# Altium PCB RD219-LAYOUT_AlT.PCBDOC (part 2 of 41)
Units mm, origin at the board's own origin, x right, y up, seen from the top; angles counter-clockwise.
Board outline 209.75 x 159.97 mm, 2 copper layers (TOP, BOTTOM), stack 0 mm thick; 398 components, 199 nets, 1469 pads, 0 vias.
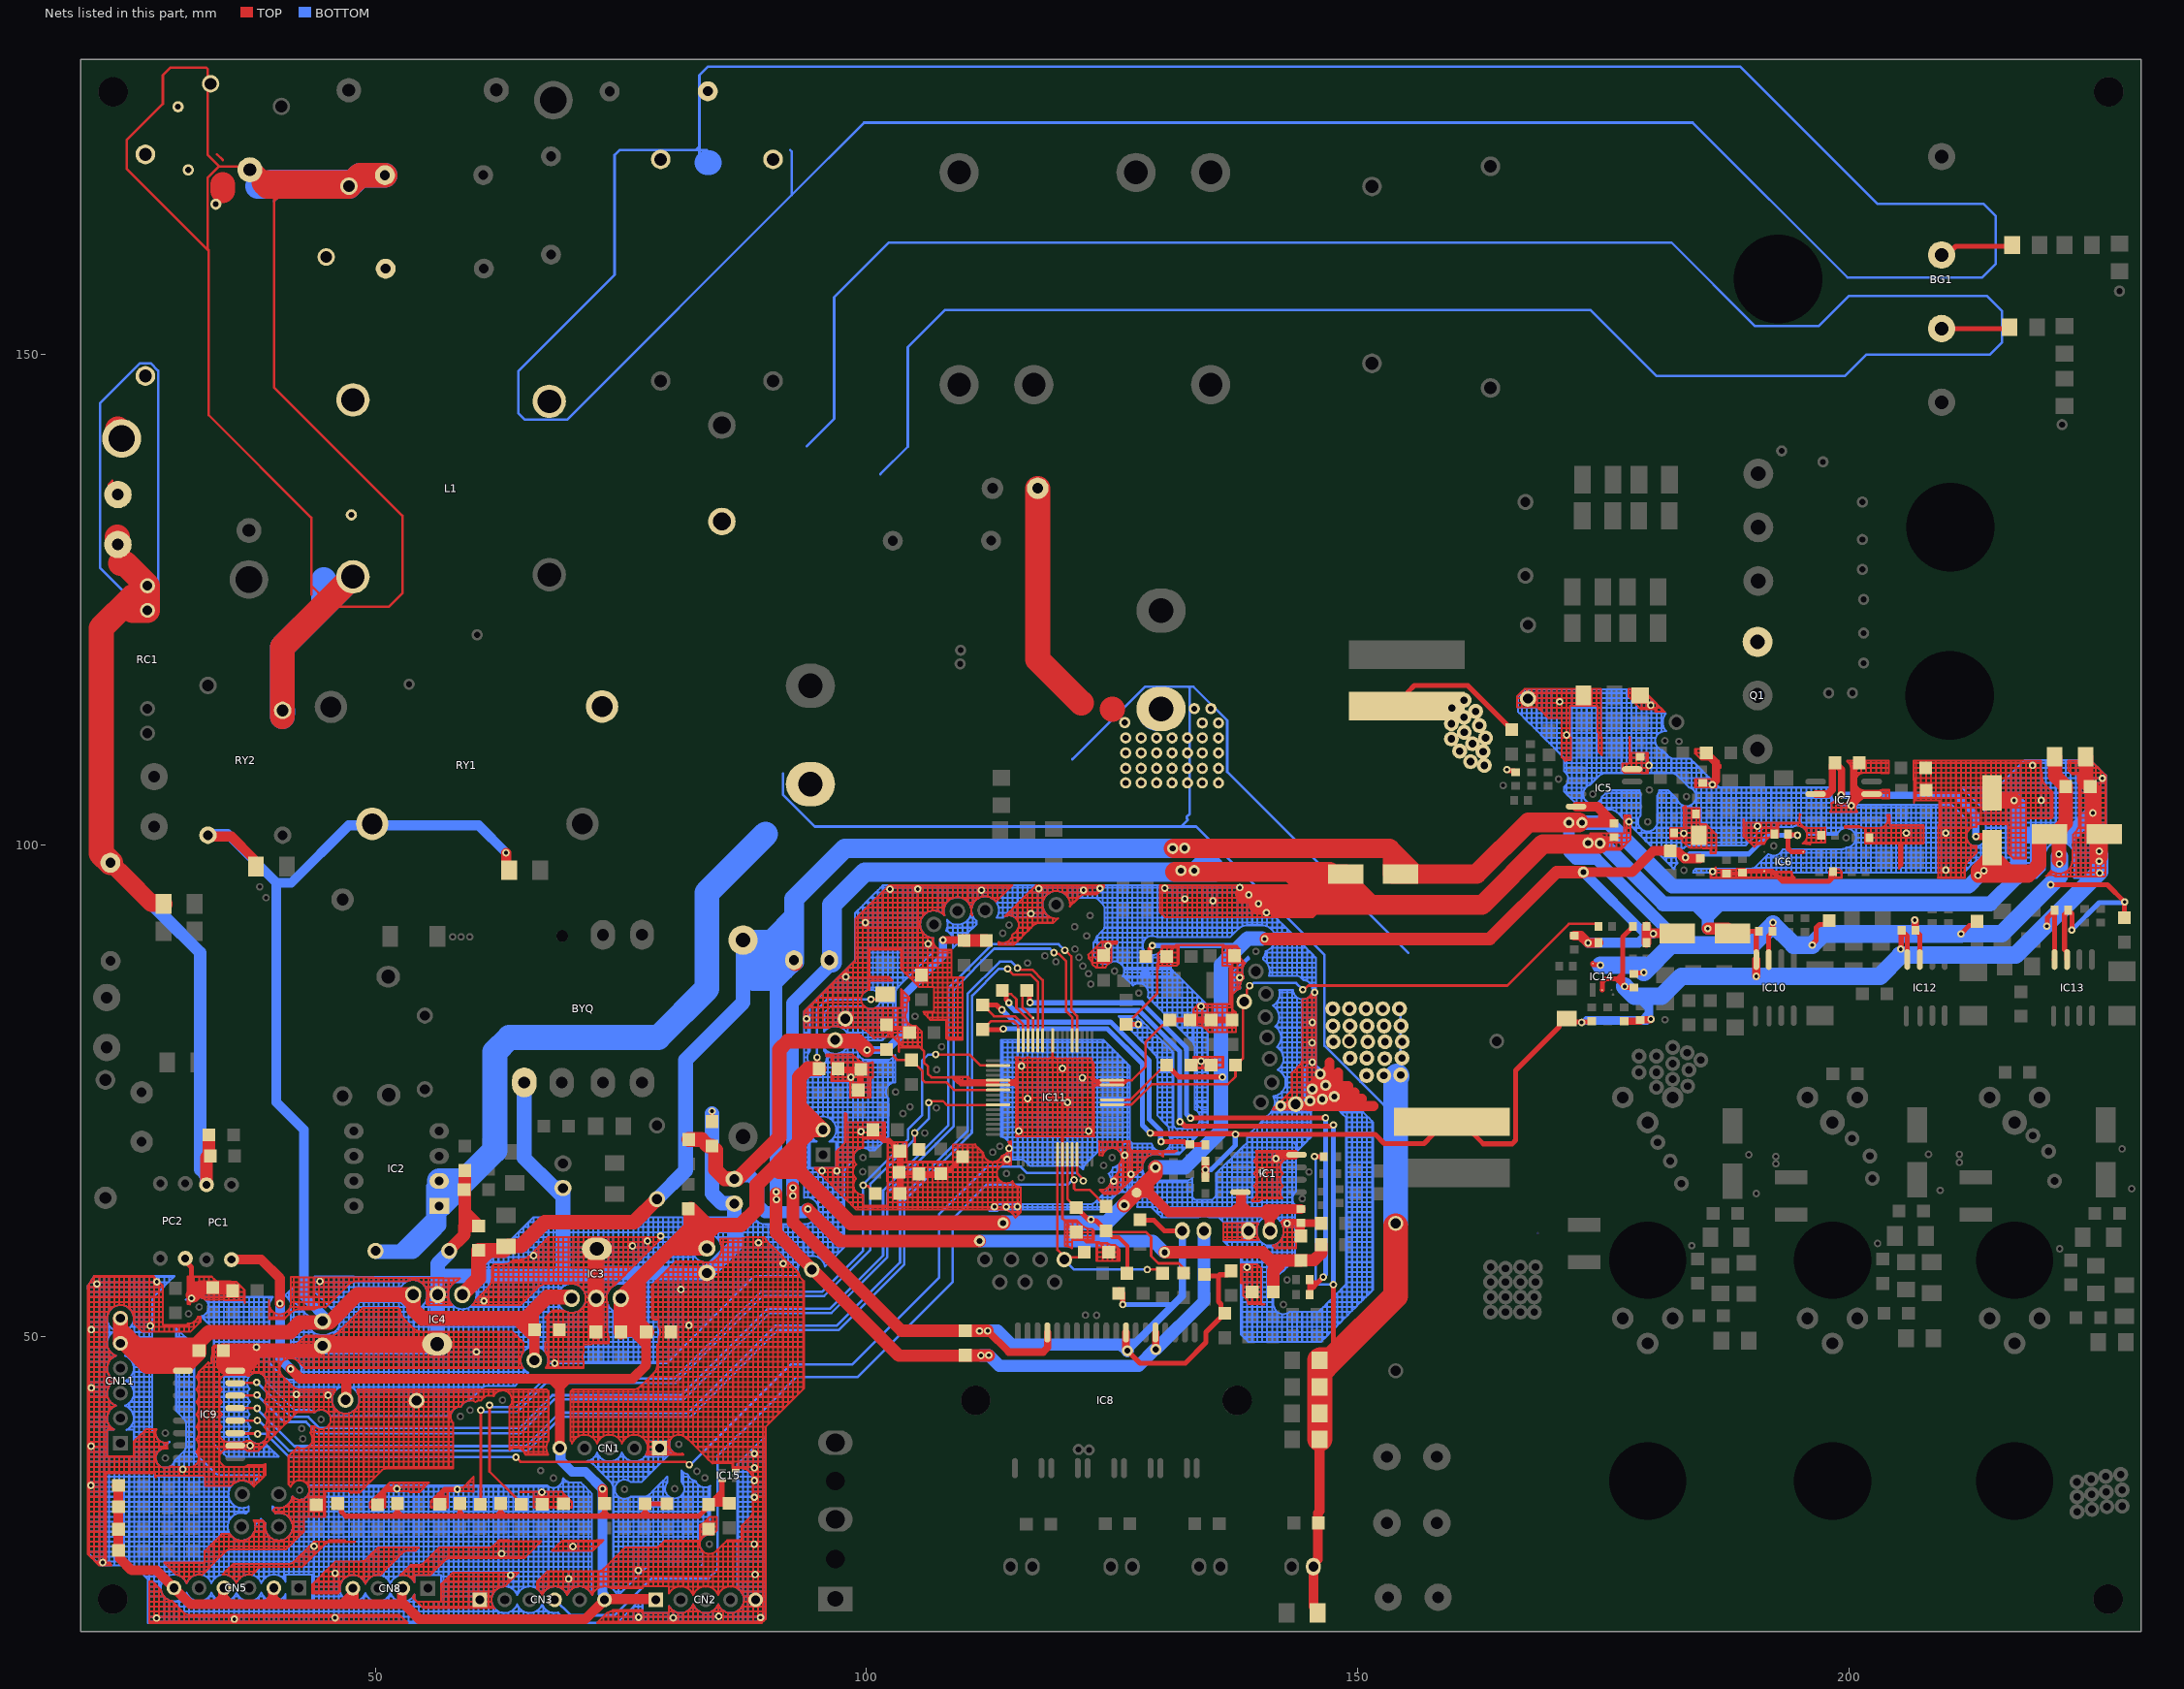
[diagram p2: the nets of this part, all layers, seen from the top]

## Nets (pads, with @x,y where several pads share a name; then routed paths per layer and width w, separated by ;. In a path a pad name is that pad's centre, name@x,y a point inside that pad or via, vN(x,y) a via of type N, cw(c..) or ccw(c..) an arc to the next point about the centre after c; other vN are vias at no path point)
+5V: C16.2 C23.1 C46.1 C49.2 C50.2 C51.2 C52.2 C53.2 C64.1 C65.1 C68.2 C87.2 C110.1 CN1.5 CN2.1 CN3.6 CN5.2 CN5.4 CN5.6 CN8.2 CN8.4 CN9.2 D13.2 EC5.1 EC16.1 EC20.1 FB1.2 IC1.8 IC3.3 IC6.8 IC11.43 IC11.56 IC15.5 LED1.1 LED2.1 LED3.1 LED4.1 LED5.1 pad.@40.296,53.386 pad.@41.376,46.714 pad.@73.135,34.512 pad.@94.965,78.418 pad.@100.444,84.334 pad.@113.9,61.576 pad.@122.835,61.935 pad.@126.222,63.389 pad.@127.49,64.656 pad.@129.41,67.234 pad.@129.091,89.799 pad.@136.214,76.427 pad.@140.523,90.485 pad.@172.957,97.267 pad.@173.434,90.067 pad.@180.09,91.02 pad.@183.356,98.756 pad.@194.752,101.026 PC1.C R13.2 R18.2 R50.2 R51.2 R81.2 R92.1 R101.2 R108.1 R145.2 R148.2 R149.2 R150.2 TP3.1 | length 561.4
  TOP w0.254: pad.@94.965,78.418 94.965,77.496 C87.2@95.184,77.277 ; pad.@100.444,84.334 101.606,84.334 D13.2@101.915,84.643 ; IC11.43@120.437,68.556 120.437,64.038 C64.1@121.346,63.129 ; R108.1@124.394,60.767 124.521,60.64 128.458,60.64 128.966,60.132 128.966,58.227 129.728,57.465 131.76,57.465 R51.2@132.776,56.449 ; IC11.56@124.987,74.106 126.852,74.106 129.881,77.135 130.018,77.135 C65.1@130.541,77.658 ; R81.2@128.328,88.728 128.328,88.88 R81.2@128.431,88.982
  TOP w0.4: R108.1@124.521,60.64 125.029,60.132 125.664,60.132 126.553,59.243 R50.2@126.553,56.83
  TOP w0.508: LED4.1@23.429,34.808 LED4.1@23.48,34.859 ; C49.2@46.162,33.03 46.558,32.634 46.558,32.177 46.995,31.74 51.806,31.74 ; C50.2@52.258,33.03 52.258,32.192 ; C51.2@58.618,33.024 58.618,32.065 ; C52.2@62.762,33.024 62.762,32.192 ; C53.2@73.709,32.661 C53.2@73.34,33.03 73.34,32.192 ; R148.2@79.677,32.983 79.67,32.99 77.477,32.99 R149.2@77.47,32.997 77.47,32.192 ; C110.1@83.881,32.7 82.921,31.74 77.785,31.74 ; C110.1@83.881,32.861 C110.1@83.936,32.917 C110.1@84,32.98 ; 85.29,35.148 85.29,34.27 ; R150.2@86.027,33.044 85.963,32.98 85.024,32.98 ; C64.1@121.346,63.129 122.575,61.9 122.784,61.9 122.792,61.892 122.881,61.803 123.358,61.803 R108.1@124.394,60.767 ; R81.2@128.431,88.707 128.827,89.103 128.827,89.466 129.091,89.73 pad.@129.091,89.799 ; C65.1@130.541,77.658 131.772,76.427 pad.@136.214,76.427 ; pad.@194.752,101.026 194.703,101.075 193.879,101.075 C16.2@193.801,101.153 193.801,99.691 194.158,99.334 IC6.8@195.33,99.334 ; 51.806,31.74 52.258,32.192 ; 51.806,31.74 52.258,31.74 ; 52.258,31.74 52.71,31.74 ; 52.258,31.74 52.258,32.192 ; 52.258,32.192 52.71,31.74 ; 52.71,31.74 58.294,31.74 ; 58.294,31.74 58.618,32.065 ; 58.294,31.74 58.608,31.74 ; 58.608,31.74 58.989,31.74 ; 58.608,31.74 58.618,31.751 58.618,32.065 ; 58.618,32.065 58.664,32.065 58.989,31.74 ; 58.989,31.74 62.31,31.74 ; 62.31,31.74 62.799,31.74 ; 62.31,31.74 62.762,32.192 ; 62.762,32.192 63.18,31.774 63.18,31.74 ; 62.762,32.192 62.762,31.778 62.799,31.74 ; 62.799,31.74 63.18,31.74 ; 63.18,31.74 72.888,31.74 ; 72.888,31.74 73.34,32.192 ; 72.888,31.74 73.34,31.74 ; 73.34,31.74 73.792,31.74 ; 73.34,31.74 73.34,32.192 ; 73.34,32.192 73.792,31.74 ; 73.792,31.74 77.15,31.74 ; 77.15,31.74 77.404,31.74 ; 77.15,31.74 77.15,31.872 77.47,32.192 ; 77.404,31.74 77.785,31.74 ; 77.404,31.74 77.47,31.807 77.47,32.192 ; 77.47,32.192 77.785,31.877 77.785,31.74 ; C110.1@84,32.98 84.645,33.625 ; C110.1@84,32.98 84.643,32.98 ; 84.643,32.98 85.024,32.98 ; 84.643,32.98 84.645,32.983 84.645,33.625 ; 84.645,33.625 84.968,33.948 ; 84.968,33.948 85.29,34.27 ; 84.968,33.948 84.968,33.037 85.024,32.98 ; 85.024,32.98 85.29,33.247 85.29,34.27
  TOP w1: LED4.1@23.861,34.859 LED3.1@23.861,32.7 LED2.1@23.861,30.414 LED1.1@23.861,28.255 24.011,28.105 24.011,27.421 25.209,26.223 27.747,26.223 CN5.6@29.525,24.445 31.176,22.794 33.843,22.794 ; CN5.4@34.605,24.445 34.509,24.349 34.509,23.46 ; PC1.C@35.367,57.846 38.4,57.846 40.296,55.95 pad.@40.296,53.386 ; CN5.2@39.685,24.445 39.589,24.349 39.589,23.401 ; pad.@41.376,46.714 42.354,45.737 47.051,45.737 ; TP3.1@46.939,43.576 46.959,43.596 47.051,43.688 47.051,45.737 ; CN8.4@47.59,23.714 46.67,22.794 ; CN8.4@47.729,24.407 47.734,24.402 47.824,24.311 47.824,23.181 48.194,22.811 48.194,22.794 ; 52.713,22.794 48.194,22.794 ; 52.713,23.249 52.713,24.311 CN8.2@52.809,24.407 ; 52.928,22.794 54.452,21.27 71.397,21.27 73.34,23.213 CN3.6@73.34,23.241 73.34,23.302 CN2.1@78.547,23.302 ; CN1.5@68.768,38.542 68.768,44.892 ; pad.@73.135,34.512 73.19,34.457 73.19,33.18 C53.2@73.34,33.03 ; LED5.1@74.991,50.48 76.312,50.48 ; IC3.3@74.991,53.909 75.179,53.721 76.227,53.721 76.801,53.147 ; C23.1@77.658,50.48 C23.1@77.582,50.48 ; R101.2@172.019,90.804 172.697,90.804 pad.@173.434,90.067 174.457,90.067 R92.1@174.494,90.104 ; pad.@172.957,97.267 177.904,97.267 180.089,99.451 R18.2@181.798,99.451 181.948,99.301 182.634,99.301 183.257,98.678 pad.@183.356,98.678 ; R145.2@179.385,90.104 179.385,90.93 ; C68.2@179.385,91.755 179.385,90.93 ; EC20.1@182.54,91.046 179.502,91.046 179.385,90.93 ; pad.@183.356,98.756 183.464,98.647 R13.2@184.815,98.647 ; 33.843,22.794 35.176,22.794 ; 33.843,22.794 34.509,23.46 ; 34.509,23.46 35.176,22.794 ; 35.176,22.794 38.982,22.794 ; 38.982,22.794 40.193,22.794 ; 38.982,22.794 39.589,23.401 ; 39.589,23.401 40.193,22.797 40.193,22.794 ; 40.193,22.794 46.67,22.794 ; 46.67,22.794 48.194,22.794 ; 47.051,45.737 67.923,45.737 ; 67.923,45.737 68.768,45.737 ; 67.923,45.737 68.768,44.892 ; 68.768,44.892 69.613,45.737 ; 68.768,44.892 68.768,45.737 ; 68.768,45.737 69.613,45.737 ; 69.613,45.737 76.217,45.737 77.582,47.102 77.582,49.21 ; 76.312,50.48 C23.1@77.582,50.48 ; 76.312,50.48 77.582,49.21 ; 77.582,49.21 C23.1@77.582,50.48
  TOP w1.016: pad.@127.49,64.656 128.76,64.656 ; 128.125,65.291 128.442,64.974 ; 128.76,65.291 128.76,64.656 ; 138.11,64.374 138.11,63.434 ; EC16.1@141.072,60.767 141.02,60.819 141.02,62.048 ; C46.1@144.206,62.991 141.962,62.991 ; 128.76,64.656 130.744,62.672 137.348,62.672 ; 137.348,62.672 138.11,63.434 ; 137.348,62.672 138.11,62.672 ; 138.11,62.672 138.745,62.672 ; 138.11,62.672 138.11,63.434 ; 138.11,63.434 138.745,62.799 138.745,62.672 ; 138.745,62.672 140.396,62.672 ; 140.396,62.672 141.02,62.048 ; 140.396,62.672 140.715,62.991 141.962,62.991 ; 141.02,62.048 141.962,62.991
  TOP w1.27: pad.@140.635,90.485 163.435,90.485 170.232,97.283 pad.@172.941,97.283
  TOP w1.5: LED5.1@74.991,50.48 74.991,51.369 ; C23.1@77.658,50.48 76.801,51.337 ; C87.2@95.184,77.277 94.031,77.277 93.152,76.398 93.152,73.467 ; pad.@113.9,61.576 113.895,61.581 98.386,61.581 93.152,66.815 ; pad.@126.222,63.389 pad.@127.49,64.656 128.125,65.291 129.41,66.576 pad.@129.41,67.234 ; 74.991,51.369 74.991,52.766 ; 74.991,51.369 76.769,51.369 76.801,51.337 ; 74.991,52.766 IC3.3@74.991,53.909 74.991,53.973 76.801,55.782 ; 74.991,52.766 76.42,52.766 76.801,53.147 ; 76.801,51.337 76.801,53.147 ; 76.801,53.147 76.801,55.782 ; 76.801,55.782 80.008,58.989 ; 80.008,58.989 EC5.1@83.731,58.989 ; 80.008,58.989 80.973,59.954 ; 80.973,59.954 82.789,59.954 ; 80.973,59.954 82.103,61.085 ; 82.103,61.085 84.364,61.085 ; 82.103,61.085 82.103,62.977 83.727,61.353 84.633,61.353 ; 82.103,61.085 82.103,60.64 82.789,59.954 ; 82.789,59.954 83.662,59.081 83.662,59.059 EC5.1@83.731,58.989 ; EC5.1@83.731,58.989 EC5.1@83.754,58.989 83.754,60.474 84.364,61.085 ; 84.364,61.085 84.633,61.353 ; 84.633,61.353 87.202,61.353 88.834,62.985 88.834,65.466 93.152,69.784 ; 93.152,66.815 93.152,68.705 ; 93.152,66.815 91.072,66.815 92.962,68.705 93.152,68.705 ; 93.152,68.705 93.152,69.784 ; 93.152,69.784 94.422,71.054 CN9.2@95.565,71.054 94.549,72.07 ; 93.152,69.784 93.152,71.562 ; 93.152,71.562 93.66,72.07 94.549,72.07 ; 93.152,71.562 93.152,73.467 ; 93.152,73.467 94.549,72.07
  BOTTOM w0.254: pad.@94.965,78.418 94.965,83.281 96.018,84.334 pad.@100.444,84.334
  BOTTOM w0.508: pad.@129.091,89.799 136.713,89.799 ; 137.025,88.776 136.713,89.088 136.713,89.799 ; 137.977,89.729 137.907,89.799 136.713,89.799 ; pad.@183.356,98.756 183.415,98.756 183.78,99.121 189.799,99.121 191.704,101.026 pad.@194.752,101.026 pad.@194.773,101.026
  BOTTOM w1: pad.@40.32,53.147 40.32,47.77 pad.@41.376,46.714 ; CN1.5@68.768,38.669 68.864,38.573 68.864,37.43 70.038,36.256 71.391,36.256 pad.@73.135,34.512 73.135,23.86 73.244,23.751 73.244,23.398 CN3.6@73.34,23.302 ; pad.@172.957,97.267 172.984,97.267 179.231,91.02 ; pad.@173.434,90.067 173.471,90.104 178.594,90.104 179.51,91.02 pad.@180.09,91.02
  BOTTOM w1.5: pad.@113.9,61.576 113.917,61.593 124.426,61.593 pad.@126.222,63.389 ; pad.@129.41,67.234 132.392,67.234 136.078,70.92 136.078,87.83 137.025,88.776 137.977,89.729 138.772,90.524 pad.@140.242,90.524
+12V: C48.1 C83.1 CN11.5 CN11.6 D1.2 D14.2 EC6.1 IC3.1 IC4.3 IC9.9 pad.@63.307,99.248 RY1.3 RY2.3 TP2.1 | length 180.2
  TOP w0.508: D1.2@63.307,97.797 63.334,97.77 D1.2@63.634,97.47
  TOP w1: RY2.3@32.974,101.036 33.107,100.903 35.363,100.903 37.553,98.713 37.553,98.151 D14.2@37.853,97.851 ; pad.@63.307,99.248 63.334,99.221 D1.2@63.334,97.77 ; TP2.1@66.15,47.61 66.192,47.653 66.192,50.656 C83.1@66.235,50.698
  TOP w1.016: D1.2@63.337,97.567 D1.2@63.434,97.47
  TOP w1.5: CN11.5@24.064,49.337 24.064,50.828 ; CN11.6@24.064,51.877 24.064,50.828 ; IC3.1@69.991,53.909 69.991,53.932 69.921,54.001 69.899,54.001 69.864,54.036 67.498,54.036 65.898,52.436 ; 24.064,50.828 24.81,50.083 25.715,49.177 ; 25.715,49.177 27.951,49.177 ; 25.715,49.177 26.803,48.089 29.039,48.089 ; 25.715,49.177 24.572,49.177 26.317,47.432 ; 26.317,47.432 27.112,47.432 ; 26.317,47.432 26.774,46.975 27.569,46.975 ; 27.112,47.432 28.382,47.432 29.039,48.089 ; 27.112,47.432 27.569,46.975 ; 27.569,46.975 30.152,46.975 ; 27.951,49.177 30.668,49.177 ; 27.951,49.177 29.039,48.089 ; 29.039,48.089 30.436,48.089 30.668,48.321 ; 29.039,48.089 30.152,46.975 ; 30.152,46.975 30.668,46.975 ; 30.668,46.975 30.684,46.975 32.065,48.356 C48.1@32.065,48.575 ; 30.668,46.975 30.668,48.321 ; 30.668,48.321 30.668,49.177 ; 30.668,49.177 31.463,49.177 C48.1@32.065,48.575 ; C48.1@32.065,48.575 32.065,49.474 33.056,50.466 41.322,50.466 42.312,51.456 45.337,51.456 48.171,54.29 52.893,54.29 ; 52.893,54.29 IC4.3@53.862,54.29 53.891,54.261 53.891,53.292 ; 52.893,54.29 53.378,53.805 53.891,53.292 ; 53.891,53.292 53.891,52.756 54.77,51.877 64.501,51.877 ; 64.501,51.877 65.898,50.48 65.898,52.436 ; 64.501,51.877 65.339,51.877 65.898,52.436
  BOTTOM w1: RY2.3@32.8,101.153 34.986,101.153 39.939,96.2 ; EC6.1@45.273,51.456 45.273,51.569 42.733,54.109 42.733,71.054 39.939,73.848 39.939,96.2 ; RY1.3@49.688,102.187 49.542,102.042 47.305,102.042 41.463,96.2 39.939,96.2
  BOTTOM w1.016: RY1.3@49.688,102.187 49.833,102.042 60.513,102.042 pad.@63.307,99.248
+15V: C15.2 C21.2 C24.1 C31.1 C57.1 C58.1 C74.1 C76.1 C82.2 C89.2 D4.2 EC4.1 EC7.1 EC12.1 EC15.1 EC17.1 IC4.1 IC5.8 IC7.6 IC8.5 IC10.3 IC12.3 IC13.3 IC14.5 pad.@90.81,64.745 pad.@90.834,63.961 pad.@111.642,48.099 pad.@112.44,48.122 pad.@129.444,48.708 pad.@131.167,99.688 pad.@132.377,99.725 pad.@171.484,102.315 pad.@172.821,102.315 pad.@174.692,87.804 pad.@179.113,87.071 pad.@192.252,92.157 pad.@196.25,89.857 pad.@199.188,105.13 pad.@206.69,92.39 pad.@211.387,90.991 pad.@212.913,100.905 pad.@213.122,96.948 pad.@213.732,97.42 pad.@220.519,95.997 pad.@221.377,99.107 pad.@221.422,98.105 pad.@222.674,91.382 pad.@228.053,94.244 R90.2 R125.2 R132.2 TP1.1 ZD2.2 ZD4.2 | length 513.5
  TOP w0.508: IC8.5@129.406,50.437 IC8.5@129.424,50.419 ; pad.@129.424,48.729 129.425,48.727 pad.@129.444,48.708 ; IC14.5@173.924,87.978 173.924,87.893 173.964,87.853 174.644,87.853 pad.@174.692,87.804 ; pad.@179.113,87.071 179.064,87.022 178.205,87.022 C89.2@178.115,86.932 ; IC10.3@191.831,88.382 191.831,90.816 192.212,91.197 C58.1@192.212,91.247 192.232,91.267 192.232,92.137 pad.@192.252,92.157 ; pad.@196.25,89.857 196.25,89.925 196.657,90.332 196.657,91.628 196.983,91.954 197.597,91.954 R90.2@197.993,92.35 ; IC7.6@196.619,105.199 IC7.6@196.601,105.217 IC7.6@196.619,105.235 ; C74.1@206.755,91.374 206.755,91.324 207.198,90.881 IC12.3@207.198,88.382 IC12.3@207.216,88.4 ; pad.@211.387,90.991 212.263,91.867 212.644,91.867 R125.2@213.04,92.263 ; EC15.1@213.818,100.905 214.564,100.159 EC15.1@214.564,99.744 ; pad.@220.519,95.997 226.3,95.997 pad.@228.053,94.244 228.04,94.23 228.04,92.658 R132.2@228.026,92.644 ; IC13.3@222.184,88.382 222.184,89.157 221.93,89.411 221.93,92.975 222.165,93.21 222.165,93.26 C76.1@222.311,93.406 C76.1@222.457,93.26 ; C76.1@222.384,93.333 222.691,93.026 222.691,91.399 pad.@222.674,91.382 ; C89.2@178.115,86.932 177.985,86.802 177.985,87.012 177.919,87.078 177.969,87.078 C89.2@178.115,86.932
  TOP w0.762: IC8.5@129.424,50.419 129.425,50.418 pad.@129.425,48.727 ; IC7.6@196.601,105.217 197.862,105.217 198.308,105.663 198.308,108.138 C21.2@198.562,108.392 199.248,107.706 199.248,105.189 pad.@199.188,105.13 ; pad.@206.69,92.39 206.736,92.344 206.736,91.343 C74.1@206.755,91.324 ; pad.@212.913,100.905 EC15.1@213.818,100.905
  TOP w1: IC5.8@172.217,103.947 174.37,103.947 174.973,103.344 ; pad.@172.821,102.315 174.813,102.315 ; 174.813,102.315 176.002,102.315 174.973,103.344 ; 174.813,102.315 174.973,102.474 174.973,103.344
  TOP w1.27: pad.@90.785,64.577 90.785,60.601 90.773,60.59 94.478,56.886 103.296,48.067 110.029,48.067 C31.1@110.062,48.099 ; C31.1@110.043,48.118 C31.1@110.062,48.099 ; pad.@112.44,48.099 pad.@111.642,48.099 C31.1@110.062,48.099
  TOP w1.5: IC4.1@58.862,54.29 58.862,54.313 58.978,54.429 59.001,54.429 60.513,55.941 60.513,57.719 ; C82.2@78.674,64.002 76.328,61.656 67.244,61.656 64.827,59.239 63.557,59.239 ZD2.2@63.104,58.786 ; D4.2@87.437,90.358 D4.2@87.723,90.072 ; EC4.1@92.57,88.102 92.588,88.102 92.727,87.964 EC4.1@92.727,87.945 ; EC15.1@214.564,99.744 214.814,99.494 EC15.1@214.814,98.694 ; ZD4.2@220.914,109.027 220.964,108.977 220.964,107.072 C57.1@222.057,105.979 222.057,102.282 221.45,101.675 221.45,101.403 221.2,101.153 EC12.1@221.127,101.153 ; 221.377,98.486 pad.@221.377,99.107 221.377,100.903 EC12.1@221.127,101.153 ; 60.513,57.719 C24.1@60.513,58.786 ZD2.2@63.104,58.786 ; 60.513,57.719 61.046,58.252 61.533,58.739 63.057,58.739 ZD2.2@63.104,58.786 ; EC15.1@214.814,98.694 216.215,97.293 ; EC15.1@214.814,98.694 214.564,98.944 213.122,97.502 pad.@213.122,96.948 214.945,96.948 ; EC15.1@214.814,98.694 214.814,97.079 214.945,96.948 ; 214.945,96.948 216.215,96.948 ; 216.215,96.948 218.233,96.948 218.578,97.293 ; 216.215,96.948 216.215,97.293 ; 216.215,97.293 218.578,97.293 ; 218.578,97.293 219.35,98.065 219.35,100.903 219.6,101.153 EC12.1@220.4,101.153 EC12.1@221.127,101.153
  TOP w2: pad.@131.274,99.698 153.2,99.698 153.572,99.327 ; pad.@172.527,102.329 167.353,102.329 162.113,97.089 EC17.1@155.81,97.089 ; 153.572,99.327 153.572,97.089 EC17.1@154.372,97.089 EC17.1@155.81,97.089 ; 153.572,99.327 155.091,97.808 EC17.1@155.81,97.089
  BOTTOM w0.508: pad.@222.674,91.382 225.46,94.168 227.798,94.168 227.825,94.195 228.005,94.195 pad.@228.053,94.244
  BOTTOM w0.762: pad.@199.188,105.13 199.228,105.09 210.881,105.09 212.913,103.058 pad.@212.913,100.905 ; pad.@206.69,92.39 206.69,91.137 206.834,90.993
  BOTTOM w1.2: pad.@171.484,102.315 171.484,99.333 172.187,98.63 174.288,98.63 181.899,91.019 181.899,89.857
  BOTTOM w1.27: pad.@90.782,64.196 90.782,85.878 ; EC4.1@92.876,88.072 92.876,87.972 91.921,87.017 ; pad.@111.642,48.099 pad.@112.44,48.099 ; pad.@112.44,48.122 113.525,47.037 127.682,47.037 pad.@129.399,48.754 ; pad.@129.444,48.708 134.341,53.606 EC7.1@134.341,60.767 ; 90.782,85.878 91.921,87.017 ; 90.782,85.878 90.739,85.835 88.404,85.835 87.437,86.802 87.652,87.017 91.921,87.017
  BOTTOM w1.5: C82.2@78.674,64.002 81.595,66.923 81.595,78.166 87.437,84.008 87.437,86.802 87.437,87.945 ; EC4.1@92.123,88.843 90.895,90.072 ; EC4.1@92.622,88.326 92.114,88.834 87.437,88.834 ; 92.626,93.152 92.626,93.134 90.136,90.644 87.723,90.644 D4.2@87.437,90.358 ; pad.@171.484,102.315 pad.@172.821,102.315 175.545,102.315 182,95.86 212.192,95.86 213.201,96.869 pad.@213.548,97.216 ; 87.437,87.945 87.564,88.072 92.876,88.072 92.876,90.358 ; 87.437,87.945 87.437,88.834 ; 87.437,88.834 D4.2@87.437,90.358 ; D4.2@87.437,90.358 87.723,90.072 90.895,90.072 ; 90.895,90.072 91.066,90.072 ; 91.066,90.072 92.59,91.596 ; 91.066,90.072 92.59,90.072 ; 92.59,90.072 92.876,90.358 ; 92.59,90.072 92.59,91.596 ; 92.59,91.596 92.626,91.632 92.876,91.882 92.876,90.358
  BOTTOM w1.8: pad.@174.692,87.804 179.113,87.804 ; pad.@179.113,87.071 181.899,89.857 190.141,89.857 192.252,91.967 194.362,89.857 pad.@196.25,89.857 197.386,90.993 206.834,90.993 ; 206.963,90.991 pad.@211.387,90.991 ; pad.@211.406,91.01 215.532,91.01 pad.@220.519,95.997 ; pad.@220.519,95.99 220.523,95.994 221.422,96.893 pad.@221.422,98.105 pad.@221.422,98.867
  BOTTOM w2: 92.626,91.632 92.626,93.134 ; 92.626,93.152 92.626,94.531 97.785,99.69 pad.@132.132,99.69
AC-N-IN: AC_N.1 C1.2 C3.2 C29.1 C80.2 CN_VN1.1 CN_VN1.2 L1.1 PC1.K R46.2 RC1.1 RC1.@26.818,123.915 Z1.1 ZD9.1 | length 148.4
  TOP w0.254: CN_VN1.1@22.864,136.713 23.245,137.094 ; AC_N.1@24.303,140.622 AC_N.1@24.791,140.622 ; C1.2@26.769,148.232 C1.2@27.239,147.762
  TOP w1.27: C80.2@23.048,98.232 23.111,98.232 23.254,98.232 23.635,97.851 C80.2@23.702,97.851 ; PC1.K@32.827,65.466 32.827,68.26 33.081,68.514 R46.2@33.081,70.546
  TOP w1.8: C80.2@23.111,98.232 24.656,96.687 27.202,94.141 28.355,94.141 ZD9.1@28.455,94.041
  TOP w2.54: C80.2@23.048,98.232 22.11,99.17 22.11,122.098 25.33,125.319 ; CN_VN1.2@23.754,131.307 CN_VN1.2@23.754,131.376 ; AC_N.1@23.794,142.364 AC_N.1@24.061,142.097 ; 24.064,128.712 24.521,128.712 RC1.1@26.818,126.415 ; 24.821,124.417 RC1.1@26.818,126.415 ; 25.323,123.915 RC1.@26.818,123.915 RC1.1@26.818,126.415
  BOTTOM w0.254: AC_N.1@23.683,141.92 AC_N.1@23.937,142.174 ; 21.987,128.233 26.669,123.552 26.925,123.808 27.909,124.791 27.909,148.303 27.145,149.067 26.063,149.067 21.987,144.991 21.987,128.233
  BOTTOM w1.27: C80.2@23.048,98.232 28.509,92.771 32.192,89.088 32.192,66.99 32.754,66.428 32.754,65.539 PC1.K@32.827,65.466
  BOTTOM w2.54: AC_N.1@23.683,141.92 AC_N.1@23.747,141.857
AC_L: BG1.3 PTC.2 R23.1 RY1.1 | length 284.3
  TOP w0.508: BG1.3@209.421,152.585 216.209,152.585 R23.1@216.339,152.715
  BOTTOM w0.254: 93.904,140.6 96.708,143.405 96.708,155.763 102.296,161.351 181.925,161.351 190.434,152.842 196.911,152.842 199.959,155.89 214.056,155.89 215.58,154.366 215.58,151.191 214.31,149.921 201.737,149.921 199.578,147.762 180.401,147.762 173.67,154.493 108.011,154.493 104.201,150.683 104.201,140.564 101.413,137.776
AC_L_F: C1.1 C4.2 F1.2 L1.2 pad.@29.927,175.158 pad.@30.967,168.732 pad.@33.772,165.249 pad.@47.57,133.632 RY2.1 Z1.2 Z3.2 | length 233.7
  TOP w0.254: 33.045,160.589 33.045,143.786 43.495,133.337 43.495,126.426 ; 33.882,170.329 34.478,169.733 ; 39.99,165.849 39.99,165.846 39.685,165.542 ; 43.495,125.537 43.495,126.426 ; 44.765,124.267 51.369,124.267 52.766,125.664 52.766,133.538 39.685,146.619 39.685,165.542 ; 44.765,125.156 44.194,125.728 43.495,126.426 ; 34.097,169.098 32.954,170.241 32.954,178.982 32.805,179.131 29.144,179.131 28.382,178.369 28.382,175.448 24.699,171.765 24.699,168.844 32.954,160.589 32.954,167.955 34.097,169.098 ; 34.097,169.098 38.288,169.098 39.685,167.701 39.685,167.447 39.685,167.075 39.685,165.542
  TOP w2.54: 34.478,166.646 34.478,167.228 ; RY2.1@40.554,113.091 40.554,120.183 47.703,127.332 L1.2@47.726,127.332 ; C4.2@50.99,168.194 48.436,168.194 Z1.2@47.317,167.075 ; Z1.2@47.317,167.075 46.946,167.447 39.685,167.447 38.669,167.447 39.041,167.075 39.685,167.075 Z1.2@47.317,167.075
  BOTTOM w0.254: 39.685,165.542 40.129,165.986 40.167,165.986
  BOTTOM w2.54: 38.034,167.066 38.043,167.075 Z1.2@47.317,167.075 Z1.2@47.742,167.5 ; 39.432,167.5 Z1.2@47.742,167.5 ; RY2.1@40.554,113.091 40.554,120.183 44.767,124.396 ; RY2.1@40.574,113.502 RY2.1@40.574,113.736 ; 44.767,127.03 44.767,124.396 ; L1.2@47.726,127.332 47.703,127.332 44.767,124.396 ; C4.2@50.99,168.194 48.436,168.194 Z1.2@47.742,167.5
AC_N: BG1.2 C2.2 C5.2 C7.2 L1.3 R26.1 | length 375.2
  TOP w0.254: C7.2@90.485,169.807 C7.2@90.665,169.987
  TOP w0.508: BG1.2@209.421,160.078 209.969,160.078 210.861,160.97 216.466,160.97 R26.1@216.593,161.097
  BOTTOM w0.254: 82.992,170.114 82.992,170.749 ; 83.754,170.749 82.992,170.749 ; 92.241,170.749 92.39,170.6 92.39,166.177 ; 82.611,170.749 82.992,171.13 ; 82.611,170.749 82.992,170.749 ; 82.611,170.749 74.864,170.749 74.356,170.241 74.356,158.049 64.577,148.27 64.577,143.952 65.212,143.317 69.53,143.317 92.39,166.177 ; 82.992,170.749 82.992,171.13 ; 82.992,171.13 82.992,178.369 83.881,179.258 188.91,179.258 202.88,165.288 213.675,165.288 214.945,164.018 214.945,159.192 213.548,157.795 199.832,157.795 184.084,173.543 99.756,173.543 92.39,166.177
  BOTTOM w2.54: 83.754,169.479 83.975,169.479
Amp_UVW0: C36.1 IC11.13 pad.@116.647,84.008 pad.@116.937,82.448 pad.@132.977,72.246 pad.@146.492,56.068 pad.@146.709,72.274 R83.1 R109.2 | length 67.5
  TOP w0.254: C36.1@116.647,84.897 116.598,84.946 C36.1@116.317,85.227 115.885,84.795 115.885,83.5 pad.@116.937,82.448 IC11.13@116.937,80.156 ; pad.@146.535,72.274 pad.@146.709,72.274
  TOP w0.508: C36.1@116.598,84.946 116.598,84.057 pad.@116.647,84.008 ; pad.@132.977,72.246 132.991,72.26 146.695,72.26 pad.@146.709,72.274 ; R83.1@145.098,54.29 R83.1@145.098,54.34 ; R109.2@145.098,55.814 R109.2@145.098,55.484 ; R83.1@145.244,54.486 R83.1@145.098,54.34 ; pad.@146.492,56.068 145.921,55.497 ; R83.1@145.098,54.34 145.098,54.747 ; 145.098,54.747 145.098,55.155 ; 145.098,54.747 145.171,54.747 145.579,55.155 ; 145.098,55.155 R109.2@145.098,55.484 ; 145.098,55.155 145.579,55.155 ; R109.2@145.098,55.484 145.11,55.497 145.921,55.497 ; 145.579,55.155 145.668,55.244 145.921,55.497
  BOTTOM w0.508: pad.@116.647,84.008 116.679,83.976 127.999,83.976 132.522,79.453 132.522,79.39 132.573,79.339 132.573,72.671 132.977,72.267 pad.@132.977,72.246 ; pad.@146.492,56.068 146.492,56.137 146.709,56.354 pad.@146.709,72.274
Amp_UVW1: C78.1 IC11.15 pad.@113.787,83.265 pad.@129.983,69.848 R45.1 R112.2 | length 39.1
  TOP w0.254: C78.1@111.821,83.754 112.026,83.549 112.964,82.611 115.123,82.611 115.937,81.797 IC11.15@115.937,80.156
  TOP w0.508: C78.1@112.026,83.549 112.026,83.559 112.217,83.75 113.233,83.75 113.718,83.265 pad.@113.787,83.265 ; pad.@129.983,69.848 132.343,69.848 132.466,69.725 132.755,69.725 132.925,69.555 134.464,69.555 R45.1@134.489,69.53
  BOTTOM w0.508: pad.@113.787,83.265 115.039,82.013 124.819,82.013 124.856,81.976 124.902,81.976 128.712,78.166 128.712,78.12 128.763,78.069 128.763,72.146 129.934,70.975 129.934,69.897 pad.@129.983,69.848
AVDD: C39.1 C86.1 C98.1 EC18.1 FB2.1 IC11.23 pad.@94.024,62.995 pad.@100.051,79.165 pad.@107.777,90.362 pad.@111.5,59.75 pad.@130.335,58.583 R7.1 R31.1 R55.1 R82.1 R97.1 TP33.1 | length 137.5
  TOP w0.254: C39.1@84.262,69.403 84.643,69.022 C39.1@84.694,68.971 ; pad.@100.051,79.165 101.974,79.165 C98.1@102.042,79.233 103.109,78.166 FB2.1@104.582,78.166 105.105,77.643 105.725,77.023 105.725,76.134 105.979,75.88 108.138,75.88 108.912,75.106 IC11.23@112.243,75.106 ; IC11.23@112.243,75.118 112.246,75.115 113.378,75.115 IC11.23@113.387,75.106
  TOP w0.8: pad.@107.777,90.362 109.861,90.362 R7.1@109.916,90.307
  TOP w1.27: pad.@94.024,62.995 97.269,59.75 pad.@111.5,59.75 ; R7.1@109.916,90.307 R31.1@112.202,90.307 ; pad.@130.335,58.583 130.341,58.589 140.288,58.589 141.122,57.755 ; R55.1@141.412,54.544 141.412,56.739 142.065,57.392 ; 141.412,57.465 141.122,57.755 ; R97.1@146.289,59.37 146.274,59.355 146.274,58.514 145.545,57.785 144.221,57.785 C86.1@144.206,57.77 144.191,57.755 141.122,57.755
  TOP w1.5: R82.1@81.904,70.067 83.217,70.067 83.881,69.403 C39.1@84.262,69.403 ; C39.1@84.643,69.022 84.643,66.997 85.568,66.072 86.512,66.072 EC18.1@86.541,66.043 ; EC18.1@86.674,66.014 86.674,66.072 86.9,66.072 91.12,70.292 91.12,79.209 91.999,80.088 99.128,80.088 pad.@100.051,79.165
  BOTTOM w0.8: pad.@100.051,79.165 102.025,79.165 103.947,81.087 103.947,84.897 107.777,88.727 pad.@107.777,90.362
  BOTTOM w1.27: EC18.1@86.592,66.219 86.695,66.116 86.78,66.116 86.999,66.334 88.217,66.334 88.961,65.59 88.961,63.416 89.705,62.672 93.66,62.672 pad.@93.914,62.926 ; pad.@111.5,59.75 129.169,59.75 pad.@130.335,58.583
BOOT: CN3.4 IC11.44 pad.@121.123,65.964 R108.2 | length 90
  TOP w0.254: IC11.44@120.937,68.556 120.937,66.288 121.123,66.102 pad.@121.123,65.964 121.123,65.107 121.272,64.958 121.767,64.958 121.77,64.956 122.695,64.956 R108.2@124.394,63.256
  BOTTOM w0.254: CN3.4@68.26,23.302 69.911,21.651 74.356,21.651 78.097,25.392 83.939,25.392 84.821,26.274 84.821,37.866 89.494,42.539 92.861,45.906 99.108,45.906 108.773,55.571 108.773,62.013 112.252,65.492 120.518,65.492 120.99,65.964 pad.@121.123,65.964
DIODE: C72.1 IC11.18 pad.@61.632,43.038 pad.@99.661,65.418 pad.@107.046,78.718 R77.2 | length 88
  TOP w0.254: pad.@61.632,43.038 61.632,36.28 64.338,33.574 64.338,33.476 R77.2@64.861,32.953 ; pad.@99.661,65.418 99.758,65.321 100.156,65.321 C72.1@100.899,64.577 ; pad.@107.046,78.718 110.483,78.718 111.595,77.606 IC11.18@113.387,77.606
  BOTTOM w0.254: pad.@61.632,43.038 61.769,43.038 61.947,42.86 64.347,42.86 67.229,45.742 80.406,45.742 89.233,54.569 95.463,54.569 99.661,58.767 pad.@99.661,65.418 99.661,65.498 104.221,70.058 104.221,71.099 105.649,72.527 105.649,78.09 106.25,78.691 107.019,78.691 pad.@107.046,78.718
EEV-A: IC9.7 IC11.4 pad.@37.93,45.359 pad.@120.182,89.317 | length 128.8
  TOP w0.254: IC9.7@35.748,45.273 35.791,45.316 37.887,45.316 pad.@37.93,45.359 ; pad.@120.182,89.317 120.237,89.317 120.838,88.716 120.838,83.246 121.437,82.647 IC11.4@121.437,80.156
  BOTTOM w0.254: pad.@37.93,45.359 41.445,41.844 43.192,41.844 44.335,40.701 64.68,40.701 68.025,44.046 81.154,44.046 89.949,52.841 96.251,52.841 101.684,58.274 101.684,64.878 108.325,71.519 108.325,85.465 112.798,89.938 119.545,89.938 120.166,89.317 pad.@120.182,89.317
EEV-B: IC9.6 IC11.5 pad.@37.967,44.076 pad.@119.08,89.081 | length 127.5
  TOP w0.254: IC9.6@35.784,43.967 IC9.6@35.748,44.003 35.784,44.039 37.93,44.039 pad.@37.967,44.076 ; pad.@119.08,89.081 119.177,88.984 119.545,88.984 120.33,88.199 120.33,83.119 120.937,82.512 IC11.5@120.937,80.156
  BOTTOM w0.254: pad.@37.967,44.076 40.707,41.336 42.939,41.336 44.082,40.193 64.783,40.193 68.212,43.622 81.341,43.622 90.128,52.409 96.43,52.409 102.116,58.095 102.116,64.651 108.877,71.412 108.877,85.358 113,89.481 118.677,89.481 119.077,89.081 pad.@119.08,89.081
EEV-C: IC9.5 IC11.11 pad.@37.973,42.712 pad.@115.36,87.519 | length 123.2
  TOP w0.254: IC9.5@35.748,42.733 IC9.5@35.758,42.723 ; IC9.5@35.78,42.701 IC9.5@35.758,42.723 ; pad.@37.973,42.712 37.963,42.723 IC9.5@35.758,42.723 ; pad.@115.36,87.519 115.498,87.519 115.677,87.34 116.871,87.34 117.937,86.274 IC11.11@117.937,80.156
  BOTTOM w0.254: pad.@37.973,42.712 37.973,42.667 41.768,38.872 65.36,38.872 68.758,42.27 81.894,42.27 90.737,51.113 96.967,51.113 103.412,57.558 103.412,64.042 110.285,70.915 110.285,84.885 113.56,88.16 114.745,88.16 115.36,87.545 pad.@115.36,87.519
EEV-D: IC9.4 IC11.12 pad.@37.995,41.485 pad.@114.359,87.437 | length 121.7
  TOP w0.254: IC9.4@35.748,41.463 35.759,41.474 37.984,41.474 pad.@37.995,41.485 ; pad.@114.359,87.437 114.971,86.826 116.717,86.826 117.437,86.106 IC11.12@117.437,80.156
  BOTTOM w0.254: pad.@37.995,41.485 38.132,41.485 38.345,41.272 38.352,41.272 41.207,38.417 65.516,38.417 68.945,41.846 82.081,41.846 90.916,50.681 97.163,50.681 103.844,57.362 103.844,63.863 110.717,70.736 110.717,70.99 110.755,71.028 110.755,84.695 113.496,87.437 pad.@114.359,87.437
EMG0: C35.2 IC11.41 pad.@128.572,56.837 R52.2 TP22.1 | length 24.4
  TOP w0.254: IC11.41@119.441,68.552 IC11.41@119.437,68.556 119.437,58.832 120.121,58.148 TP22.1@120.121,57.846 120.36,58.085 121.636,58.085 C35.2@122.159,58.608 ; TP22.1@120.203,58.238 120.203,58.1 TP22.1@120.29,58.187 ; pad.@128.572,56.837 129.73,56.837 R52.2@130.119,56.448
  BOTTOM w0.254: TP22.1@120.121,57.846 121.122,56.845 pad.@128.8,56.845
EMG1: C56.1 IC11.55 pad.@138.999,85.717 pad.@144.396,85.32 R93.2 TP29.1 | length 63
  TOP w0.254: IC11.55@124.987,73.606 126.963,73.606 129.053,75.696 136.783,75.696 137.551,76.464 C56.1@137.551,77.658 ; C56.1@137.028,77.135 C56.1@137.551,77.658 ; TP29.1@138.44,83.957 138.313,83.83 138.313,78.33 138.164,78.181 138.074,78.181 C56.1@137.551,77.658 ; TP29.1@138.451,84.095 138.695,84.339 138.695,85.276 138.999,85.58 pad.@138.999,85.717 ; pad.@144.396,85.32 144.533,85.32 144.948,85.735 165.204,85.735 171.478,92.009 174.24,92.009 R93.2@174.494,91.755
  BOTTOM w0.254: pad.@138.999,85.717 139.117,85.717 139.402,86.002 143.714,86.002 pad.@144.396,85.32
EXHAUST: C71.1 IC11.26 pad.@60.741,42.53 pad.@104.907,70.734 pad.@106.335,73.822 R75.2 | length 83.5
  TOP w0.254: R75.2@60.697,32.964 60.741,33.008 pad.@60.741,42.53 ; pad.@104.907,70.734 104.907,69.492 C71.1@105.334,69.066 C71.1@105.857,69.589 ; pad.@106.335,73.822 106.488,73.975 107.781,73.975 108.162,73.594 112.243,73.594 112.246,73.597 113.378,73.597 IC11.26@113.387,73.606
  BOTTOM w0.254: pad.@60.741,42.53 60.879,42.53 61.057,42.352 64.45,42.352 67.416,45.318 80.593,45.318 89.412,54.137 95.666,54.137 100.388,58.859 100.388,65.566 104.81,69.988 104.81,70.637 pad.@104.907,70.734 104.907,70.744 106.367,72.204 106.367,73.79 pad.@106.335,73.822
FWV: IC9.3 IC11.45 pad.@38.024,40.11 pad.@64.317,37.739 pad.@81.967,36.978 pad.@122.058,65.863 | length 107.6
  TOP w0.254: IC9.3@35.748,40.193 35.814,40.127 35.838,40.151 37.982,40.151 pad.@38.024,40.11 ; pad.@64.317,37.739 64.781,37.275 81.564,37.275 81.861,36.978 pad.@81.967,36.978 ; IC11.45@121.437,68.556 121.437,66.621 122.058,66 pad.@122.058,65.863
  BOTTOM w0.254: pad.@38.024,40.11 38.879,40.11 41.25,37.739 pad.@64.317,37.739 ; pad.@81.967,36.978 82.101,36.978 92.324,47.202 98.572,47.202 107.376,56.006 107.376,62.449 112.223,67.296 115.706,67.296 116.352,66.65 121.407,66.65 122.058,66 pad.@122.058,65.863
GND: BYQ.5 C9.1 C12.2 C13.1 C14.1 C15.1 C16.1 C17.1 C18.1 C19.2 C20.1 C21.1 C22.2 C23.2 C24.2 C26.1 C27.2 C28.2 C30.2 C31.2 C35.1 C36.2 C37.1 C38.1 C39.2 C40.1 C41.1 C42.1 C43.1 C44.2 C45.2 C46.2 C48.2 C55.1 C56.2 C57.2 C58.2 C62.1 C63.1 C63.2 C64.2 C65.2 C68.1 C69.2 C70.2 C71.2 C72.2 C73.2 C74.2 C76.2 C78.2 C79.1 C81.1 C83.2 C84.2 C85.2 C86.2 C88.2 C89.1 C90.1 C91.1 C97.1 C98.2 C99.2 C100.1 C110.2 C111.1 CN1.1 CN2.5 CN3.1 D7.1 D20.1 D25.1 EC1.2 EC2.2 EC3.2 EC4.2 EC5.2 EC6.2 EC7.2 EC12.2 EC15.2 EC16.2 EC17.2 EC18.2 EC19.2 EC20.2 IC1.4 IC2.1 IC2.2 IC3.2 IC3.4 IC4.2 IC4.4 IC5.4 IC6.4 IC7.3 IC8.8 IC8.16 IC9.2 IC9.8 IC10.4 IC11.9 IC11.14 IC11.16 IC11.21 IC11.22 IC11.42 IC11.59 IC11.60 IC12.4 IC13.4 IC14.2 IC15.3 pad.@21.1,44.805 pad.@21.1,50.725 pad.@21.058,34.872 pad.@21.079,38.866 pad.@21.664,55.373 pad.@22.262,27.032 pad.@27.112,51.115 pad.@27.741,21.373 pad.@27.763,55.588 pad.@30.414,36.51 pad.@31.303,53.909 pad.@35.661,21.269 pad.@37.272,38.923 pad.@37.908,48.932 pad.@41.971,44.13 pad.@43.767,28.682 pad.@44.367,55.63 pad.@45.189,44.053 pad.@45.908,21.397 pad.@45.917,25.928 pad.@52.203,34.535 pad.@58.354,34.478 pad.@60.292,48.457 pad.@61.058,53.641 pad.@62.857,27.931 pad.@63.772,25.732 pad.@66.113,58.257 pad.@66.956,34.176 pad.@68.26,47.305 pad.@69.687,25.361 pad.@70.113,28.652 pad.@76.168,59.239 pad.@76.769,26.223 pad.@76.803,21.452 pad.@77.699,59.746 pad.@79.055,60.259 pad.@80.325,21.397 pad.@81.106,54.816 pad.@81.926,51.161 pad.@84.281,72.947 pad.@84.954,21.559 pad.@88.58,28.89 pad.@88.67,25.81 pad.@88.595,33.67 pad.@88.595,35.371 pad.@88.595,36.663 pad.@88.595,38.109 pad.@89.003,59.564 pad.@89.22,21.43 pad.@91.515,57.44 pad.@92.501,64.341 pad.@92.505,65.147 pad.@93.895,82.351 pad.@95.477,66.895 pad.@96.97,66.875 pad.@97.896,86.629 pad.@98.403,76.402 pad.@99.446,70.873 pad.@99.883,92.136 pad.@102.385,95.539 pad.@105.217,95.565 pad.@106.283,89.983 pad.@111.499,50.588 pad.@111.694,95.438 pad.@112.327,50.596 pad.@113.02,63.225 pad.@113.925,81.327 pad.@114.232,63.211 pad.@114.305,68.048 pad.@114.487,83.976 pad.@114.505,69.167 pad.@115.356,63.233 pad.@115.504,70.927 pad.@115.773,77.551 pad.@116.393,74.229 pad.@116.729,93.05 pad.@117.54,95.594 pad.@119.94,77.312 pad.@120.457,73.848 pad.@121.977,76.343 pad.@122.083,95.437 pad.@122.616,70.927 pad.@123.758,95.623 pad.@124.578,89.788 pad.@125.157,65.823 pad.@126.28,68.47 pad.@126.078,53.283 pad.@126.92,66.526 pad.@126.287,112.498 pad.@126.377,106.36 pad.@126.377,107.837 pad.@126.377,109.408 pad.@126.377,110.94 pad.@126.553,48.575 pad.@127.655,81.787 pad.@127.951,106.36 pad.@127.951,107.837 pad.@127.951,109.408 pad.@127.951,110.94 pad.@128.877,70.723 pad.@129.526,106.36 pad.@129.526,107.837 pad.@129.526,109.408 pad.@129.526,110.94 pad.@130.364,95.645 pad.@131.1,106.36 pad.@131.1,107.837 pad.@131.1,109.408 pad.@131.1,110.94 pad.@131.897,71.882 pad.@131.996,97.439 pad.@132.395,94.549 pad.@132.675,106.36 pad.@132.675,107.837 pad.@132.675,109.408 pad.@132.675,110.94 pad.@133.35,97.431 pad.@133.367,113.914 pad.@134.046,78.039 pad.@134.046,83.627 pad.@134.173,106.36 pad.@134.173,107.837 pad.@134.173,109.408 pad.@134.173,110.94 pad.@134.173,112.456 pad.@134.499,66.997 pad.@135.05,113.914 pad.@135.255,94.355 pad.@135.824,106.36 pad.@135.824,107.837 pad.@135.824,109.408 pad.@135.824,110.94 pad.@135.824,112.456 pad.@137.59,88.618 pad.@137.557,70.597 pad.@137.983,86.548 pad.@137.992,95.712 pad.@138.73,57.073 pad.@138.912,94.967 pad.@139.897,94.061 pad.@140.7,93.158 pad.@140.241,66.828 pad.@141.666,68.133 pad.@142.152,73.492 pad.@142.809,61.529 pad.@144.206,61.591 pad.@145.136,74.008 pad.@145.348,79.916 pad.@145.366,77.929 pad.@145.366,81.977 pad.@145.367,75.203 pad.@145.598,68.345 pad.@145.611,85.049 pad.@146.184,76.733 pad.@146.396,74.167 pad.@146.731,75.583 pad.@147.45,83.373 pad.@147.47,81.628 pad.@147.507,80.014 pad.@147.508,55.306 pad.@147.522,71.548 pad.@147.603,74.446 pad.@149.147,83.373 pad.@149.203,81.628 pad.@149.218,78.337 pad.@150.845,83.373 pad.@150.897,76.582 pad.@150.911,78.346 pad.@150.936,81.628 pad.@151.016,80.014 pad.@152.542,83.373 pad.@152.653,76.572 pad.@152.668,81.628 pad.@152.751,78.293 pad.@152.771,80.014 pad.@154.239,83.373 pad.@154.366,76.642 pad.@154.401,81.628 pad.@154.497,78.364 pad.@154.525,80.014 pad.@159.526,110.834 pad.@159.526,112.381 pad.@159.573,113.98 pad.@160.376,109.591 pad.@160.811,113.028 pad.@160.822,114.777 pad.@160.838,111.497 pad.@161.478,108.519 pad.@161.677,110.341 pad.@161.987,113.633 pad.@162.367,112.202 pad.@162.748,109.535 pad.@162.875,108.138 pad.@163.002,110.932 pad.@165.183,107.708 pad.@170.545,114.621 pad.@171.253,111.23 pad.@172.789,81.977 pad.@173.432,100.248 pad.@174.657,100.219 pad.@177.158,85.649 pad.@177.604,102.414 pad.@179.639,108.138 pad.@179.815,114.263 pad.@179.842,82.312 pad.@183.182,101.216 pad.@185.624,91.535 pad.@186.082,106.186 pad.@186.116,97.343 pad.@190.561,86.675 pad.@190.672,101.951 pad.@200.22,104.049 pad.@205.255,89.446 pad.@205.832,101.246 pad.@209.847,101.253 pad.@209.851,97.491 pad.@216.805,104.568 pad.@218.678,108.144 pad.@219.567,104.588 pad.@220.131,91.776 pad.@224.806,103.298 pad.@225.462,98.39 pad.@225.466,99.4 pad.@225.511,97.19 pad.@225.776,106.822 PC2.K Q1.3 R1.1 R3.1 R8.2 R14.1 R22.1 R32.2 R42.1 R49.1 R54.2 R56.2 R59.1 R60.1 R61.1 R62.1 R66.1 R72.1 R74.1 R76.1 R78.1 R80.1 R95.2 R98.2 R106.2 R113.1 R115.1 R116.1 R135.2 R136.2 R144.1 R147.1 TP30.1 TP31.1 TP32.1 ZD4.1 ZD8.1 | length 23966.1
